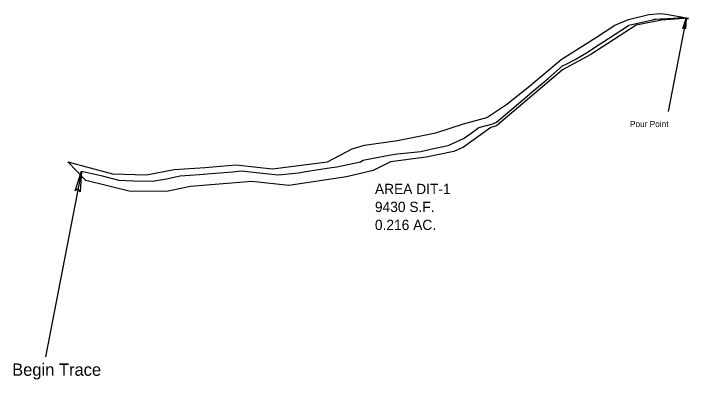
# Model space of a CAD drawing. Extents: x 2763 to 5445, y 2720 to 3371.
import ezdxf

# ---------------------------------------------------------------- set-up
doc = ezdxf.new("R2010")
doc.units = 0
for name, color, linetype in [('Default', 7, 'Continuous'), ('DESIGN - SCRATCH - User 1', 7, 'Continuous'), ('SURVEY - CENTERLINE - Preliminary', 7, 'Continuous'), ('SURVEY - CENTERLINE - Preliminary Text', 7, 'Continuous'), ('SURVEY - DRAINAGE - Area Shapes', 7, 'Continuous')]:
    doc.layers.add(name, color=color, linetype=linetype)

msp = doc.modelspace()

# ---------------------------------------------------------------- linework, layer by layer
at = {"layer": 'DESIGN - SCRATCH - User 1'}
msp.add_line((3416.68, 3071.74), (3399.14, 2981.3), dxfattribs=at)
msp.add_lwpolyline([(3416.68, 3071.74), (3415.99, 3061.64), (3415.01, 3063.15), (3413.49, 3062.12)], close=True, dxfattribs=at)
msp.add_lwpolyline([(3416.68, 3071.74), (3415.99, 3061.64), (3415.01, 3063.15), (3413.49, 3062.12), (3416.68, 3071.74)], dxfattribs=at)
at = {"layer": 'SURVEY - CENTERLINE - Preliminary'}
msp.add_lwpolyline([(2828.93, 2923.1), (2847.47, 2918.72), (2864.98, 2914.2), (2879.54, 2913.8), (2897.93, 2913.29), (2911.62, 2915.74), (2924.81, 2918.67), (2943.7, 2920.01), (2954.83, 2920.8), (2975.77, 2922.47), (2984.52, 2923.27), (3007.85, 2920.8), (3020.33, 2919.4), (3039.93, 2921.56), (3048.74, 2923.2), (3072.01, 2926.54), (3076.93, 2927.22), (3100.16, 2932.32), (3102.78, 2933.66), (3104.08, 2934.05), (3129.55, 2939.15), (3136.16, 2939.84), (3158.59, 2942.3), (3168.24, 2944.57), (3185.13, 2948.03), (3200.31, 2954.93), (3206.41, 2959.19), (3215.07, 2965.51), (3228.82, 2969.21), (3232.39, 2970.96), (3247.12, 2983.45), (3264.47, 2998.17), (3264.75, 2998.4), (3265.09, 2998.69), (3282.38, 3013.35), (3296.54, 3025.48), (3300.75, 3027.54), (3308.86, 3031.88), (3321.43, 3039.32), (3328.62, 3044.25), (3341.15, 3052.1), (3360.7, 3064.97), (3360.76, 3065.01), (3360.86, 3065.07), (3383.79, 3070.43), (3384.87, 3070.68), (3385.79, 3070.86), (3386.2, 3070.94), (3387.05, 3070.99), (3391.22, 3071.26), (3392.78, 3071.36), (3404.26, 3072.1), (3408.69, 3072.41), (3410.96, 3072.58), (3411, 3072.62), (3411.01, 3072.63), (3411.02, 3072.63), (3411.29, 3072.75), (3411.32, 3072.79), (3412.34, 3072.76), (3416.67, 3071.74), (3418.7, 3071.27)], dxfattribs=at)
at = {"layer": 'SURVEY - CENTERLINE - Preliminary Text'}
msp.add_line((2828.93, 2923.1), (2793.86, 2742.2), dxfattribs=at)
msp.add_lwpolyline([(2828.93, 2923.1), (2827.56, 2902.89), (2825.6, 2905.92), (2822.55, 2903.86)], close=True, dxfattribs=at)
msp.add_lwpolyline([(2828.93, 2923.1), (2827.56, 2902.89), (2825.6, 2905.92), (2822.55, 2903.86), (2828.93, 2923.1)], dxfattribs=at)
at = {"layer": 'SURVEY - DRAINAGE - Area Shapes'}
for points in [[(3418.91, 3071.91), (3392.78, 3069.96), (3368, 3065.07), (3324.01, 3036.65), (3296.54, 3021.8), (3232.39, 2967.3), (3226.71, 2965.51), (3200.31, 2946.6), (3190.73, 2942.24), (3164.05, 2936.65), (3129.3, 2932.32), (3112.24, 2923.88), (3086.33, 2917.5), (3030.29, 2909.1)], [(3328.62, 3053.06), (3347.21, 3065.07), (3360.7, 3070.87), (3380.24, 3075.46), (3391.7, 3076.61), (3397.13, 3076.03), (3418.91, 3071.91)], [(2815.39, 2932.32), (2858.99, 2920.4), (2891.93, 2919.5), (2919.02, 2924.66), (2949.04, 2926.79), (2978.78, 2929.2), (3014.57, 2925.37), (3067.83, 2932.32), (3091.99, 2944.83), (3104.08, 2948.44), (3136.16, 2953.1), (3173.27, 2960.3), (3200.31, 2969.24), (3222.91, 2975.32), (3242.33, 2988.41), (3264.47, 3005.79), (3295.08, 3031.88), (3328.62, 3053.06)], [(3030.29, 2909.1), (2994.41, 2913.04), (2934.81, 2908.32), (2911.62, 2903.17), (2875.33, 2903.49), (2833, 2914.1), (2815.39, 2932.32)]]:
    msp.add_lwpolyline(points, dxfattribs=at)

# ---------------------------------------------------------------- texts
at = {"layer": 'Default'}
for s, p in [('AREA DIT-1', (3114.08, 2900.81)), ('9430 S.F.', (3114.08, 2883.31)), ('0.216 AC.', (3114.08, 2865.81))]:
    msp.add_text(s, height=10, dxfattribs=at).set_placement(p)
at = {"layer": 'DESIGN - SCRATCH - User 1'}
msp.add_text('Pour Point', height=6, dxfattribs=at).set_placement((3362.01, 2966.01))
at = {"layer": 'SURVEY - CENTERLINE - Preliminary Text'}
msp.add_text('Begin Trace', height=12, dxfattribs=at).set_placement((2761.41, 2723.88))

doc.saveas('drawing.dxf')
